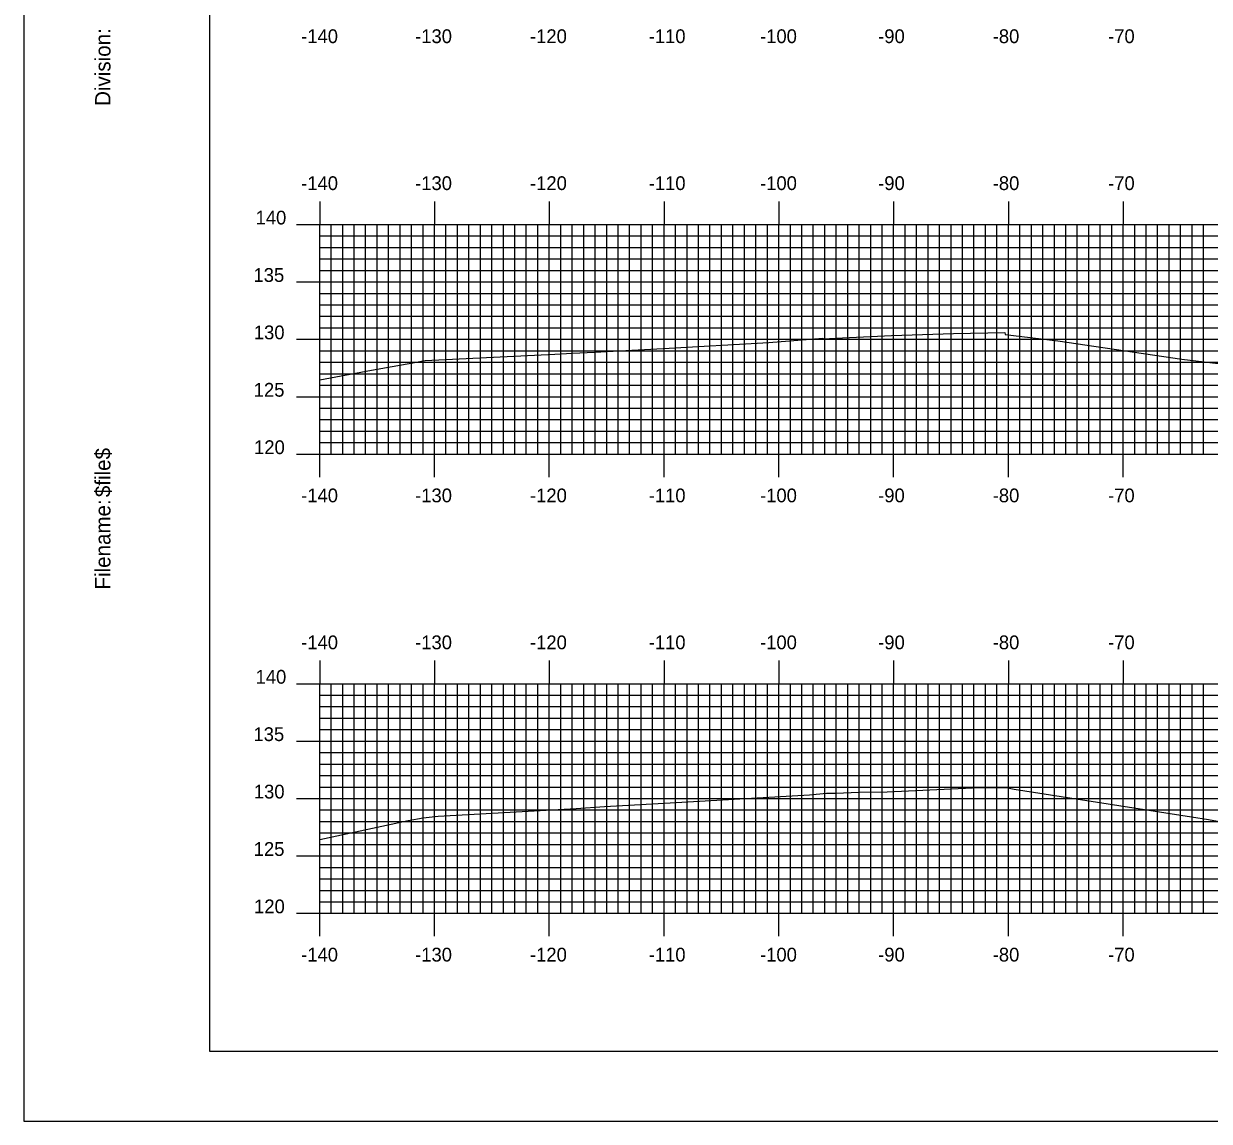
# Model space of a CAD drawing. Extents: x 841388 to 841731, y 363538 to 363758.
# Drawn here: x 841388.1 to 841491.4, y 363537.6 to 363633.2 of the extents above; entities that cross this region are included whole.
import ezdxf

# ---------------------------------------------------------------- set-up
doc = ezdxf.new("R2010")
doc.units = 0
for name, color, linetype in [('BORDER', 7, 'Continuous'), ('H_V ANNOTATION', 7, 'Continuous'), ('M_Roadway_Centerline', 7, 'Continuous'), ('MAJOR', 7, 'Continuous'), ('MINOR', 7, 'Continuous'), ('PLOT BOUNDARY', 7, 'Continuous'), ('S_Roadway_Centerline', 7, 'Continuous')]:
    doc.layers.add(name, color=color, linetype=linetype)

msp = doc.modelspace()

# ---------------------------------------------------------------- linework, layer by layer
at = {"layer": 'BORDER'}
msp.add_lwpolyline([(841404.26, 363543.72), (841724.26, 363543.72), (841724.26, 363753.72), (841404.26, 363753.72)], close=True, dxfattribs=at)
at = {"layer": 'MAJOR'}
for p, q in [((841413.86, 363617.73), (841413.86, 363615.72)), ((841423.86, 363617.73), (841423.86, 363615.72)), ((841433.86, 363617.73), (841433.86, 363615.72)), ((841443.86, 363617.73), (841443.86, 363615.72)), ((841453.86, 363617.73), (841453.86, 363615.72)), ((841463.86, 363617.73), (841463.86, 363615.72)), ((841473.86, 363617.73), (841473.86, 363615.72)), ((841483.86, 363617.73), (841483.86, 363615.72)), ((841411.85, 363615.72), (841413.86, 363615.72)), ((841413.86, 363615.72), (841693.86, 363615.72)), ((841413.86, 363595.72), (841413.86, 363615.72)), ((841413.86, 363595.72), (841413.86, 363615.72)), ((841413.86, 363615.72), (841693.86, 363615.72)), ((841423.86, 363595.72), (841423.86, 363615.72)), ((841433.86, 363595.72), (841433.86, 363615.72)), ((841443.86, 363595.72), (841443.86, 363615.72)), ((841453.86, 363595.72), (841453.86, 363615.72)), ((841463.86, 363595.72), (841463.86, 363615.72)), ((841473.86, 363595.72), (841473.86, 363615.72)), ((841483.86, 363595.72), (841483.86, 363615.72)), ((841411.85, 363610.72), (841413.86, 363610.72)), ((841413.86, 363610.72), (841693.86, 363610.72)), ((841411.85, 363605.72), (841413.86, 363605.72)), ((841413.86, 363605.72), (841693.86, 363605.72)), ((841411.85, 363600.72), (841413.86, 363600.72)), ((841413.86, 363600.72), (841693.86, 363600.72)), ((841411.85, 363595.72), (841413.86, 363595.72)), ((841413.86, 363595.72), (841693.86, 363595.72)), ((841413.86, 363595.72), (841693.86, 363595.72)), ((841413.86, 363593.72), (841413.86, 363595.72)), ((841423.86, 363593.72), (841423.86, 363595.72)), ((841433.86, 363593.72), (841433.86, 363595.72)), ((841443.86, 363593.72), (841443.86, 363595.72)), ((841453.86, 363593.72), (841453.86, 363595.72)), ((841463.86, 363593.72), (841463.86, 363595.72)), ((841473.86, 363593.72), (841473.86, 363595.72)), ((841483.86, 363593.72), (841483.86, 363595.72)), ((841413.86, 363577.73), (841413.86, 363575.72)), ((841423.86, 363577.73), (841423.86, 363575.72)), ((841433.86, 363577.73), (841433.86, 363575.72)), ((841443.86, 363577.73), (841443.86, 363575.72)), ((841453.86, 363577.73), (841453.86, 363575.72)), ((841463.86, 363577.73), (841463.86, 363575.72)), ((841473.86, 363577.73), (841473.86, 363575.72)), ((841483.86, 363577.73), (841483.86, 363575.72)), ((841411.85, 363575.72), (841413.86, 363575.72)), ((841413.86, 363575.72), (841693.86, 363575.72)), ((841413.86, 363555.72), (841413.86, 363575.72)), ((841413.86, 363555.72), (841413.86, 363575.72)), ((841413.86, 363575.72), (841693.86, 363575.72)), ((841423.86, 363555.72), (841423.86, 363575.72)), ((841433.86, 363555.72), (841433.86, 363575.72)), ((841443.86, 363555.72), (841443.86, 363575.72)), ((841453.86, 363555.72), (841453.86, 363575.72)), ((841463.86, 363555.72), (841463.86, 363575.72)), ((841473.86, 363555.72), (841473.86, 363575.72)), ((841483.86, 363555.72), (841483.86, 363575.72)), ((841411.85, 363570.72), (841413.86, 363570.72)), ((841413.86, 363570.72), (841693.86, 363570.72)), ((841411.85, 363565.72), (841413.86, 363565.72)), ((841413.86, 363565.72), (841693.86, 363565.72)), ((841411.85, 363560.72), (841413.86, 363560.72)), ((841413.86, 363560.72), (841693.86, 363560.72)), ((841411.85, 363555.72), (841413.86, 363555.72)), ((841413.86, 363555.72), (841693.86, 363555.72)), ((841413.86, 363555.72), (841693.86, 363555.72)), ((841413.86, 363553.72), (841413.86, 363555.72)), ((841423.86, 363553.72), (841423.86, 363555.72)), ((841433.86, 363553.72), (841433.86, 363555.72)), ((841443.86, 363553.72), (841443.86, 363555.72)), ((841453.86, 363553.72), (841453.86, 363555.72)), ((841463.86, 363553.72), (841463.86, 363555.72)), ((841473.86, 363553.72), (841473.86, 363555.72)), ((841483.86, 363553.72), (841483.86, 363555.72))]:
    msp.add_line(p, q, dxfattribs=at)
at = {"layer": 'MINOR'}
for p, q in [((841414.86, 363595.72), (841414.86, 363615.72)), ((841415.86, 363595.72), (841415.86, 363615.72)), ((841416.86, 363595.72), (841416.86, 363615.72)), ((841417.86, 363595.72), (841417.86, 363615.72)), ((841418.86, 363595.72), (841418.86, 363615.72)), ((841419.86, 363595.72), (841419.86, 363615.72)), ((841420.86, 363595.72), (841420.86, 363615.72)), ((841421.86, 363595.72), (841421.86, 363615.72)), ((841422.86, 363595.72), (841422.86, 363615.72)), ((841424.86, 363595.72), (841424.86, 363615.72)), ((841425.86, 363595.72), (841425.86, 363615.72)), ((841426.86, 363595.72), (841426.86, 363615.72)), ((841427.86, 363595.72), (841427.86, 363615.72)), ((841428.86, 363595.72), (841428.86, 363615.72)), ((841429.86, 363595.72), (841429.86, 363615.72)), ((841430.86, 363595.72), (841430.86, 363615.72)), ((841431.86, 363595.72), (841431.86, 363615.72)), ((841432.86, 363595.72), (841432.86, 363615.72)), ((841434.86, 363595.72), (841434.86, 363615.72)), ((841435.86, 363595.72), (841435.86, 363615.72)), ((841436.86, 363595.72), (841436.86, 363615.72)), ((841437.86, 363595.72), (841437.86, 363615.72)), ((841438.86, 363595.72), (841438.86, 363615.72)), ((841439.86, 363595.72), (841439.86, 363615.72)), ((841440.86, 363595.72), (841440.86, 363615.72)), ((841441.86, 363595.72), (841441.86, 363615.72)), ((841442.86, 363595.72), (841442.86, 363615.72)), ((841444.86, 363595.72), (841444.86, 363615.72)), ((841445.86, 363595.72), (841445.86, 363615.72)), ((841446.86, 363595.72), (841446.86, 363615.72)), ((841447.86, 363595.72), (841447.86, 363615.72)), ((841448.86, 363595.72), (841448.86, 363615.72)), ((841449.86, 363595.72), (841449.86, 363615.72)), ((841450.86, 363595.72), (841450.86, 363615.72)), ((841451.86, 363595.72), (841451.86, 363615.72)), ((841452.86, 363595.72), (841452.86, 363615.72)), ((841454.86, 363595.72), (841454.86, 363615.72)), ((841455.86, 363595.72), (841455.86, 363615.72)), ((841456.86, 363595.72), (841456.86, 363615.72)), ((841457.86, 363595.72), (841457.86, 363615.72)), ((841458.86, 363595.72), (841458.86, 363615.72)), ((841459.86, 363595.72), (841459.86, 363615.72)), ((841460.86, 363595.72), (841460.86, 363615.72)), ((841461.86, 363595.72), (841461.86, 363615.72)), ((841462.86, 363595.72), (841462.86, 363615.72)), ((841464.86, 363595.72), (841464.86, 363615.72)), ((841465.86, 363595.72), (841465.86, 363615.72)), ((841466.86, 363595.72), (841466.86, 363615.72)), ((841467.86, 363595.72), (841467.86, 363615.72)), ((841468.86, 363595.72), (841468.86, 363615.72)), ((841469.86, 363595.72), (841469.86, 363615.72)), ((841470.86, 363595.72), (841470.86, 363615.72)), ((841471.86, 363595.72), (841471.86, 363615.72)), ((841472.86, 363595.72), (841472.86, 363615.72)), ((841474.86, 363595.72), (841474.86, 363615.72)), ((841475.86, 363595.72), (841475.86, 363615.72)), ((841476.86, 363595.72), (841476.86, 363615.72)), ((841477.86, 363595.72), (841477.86, 363615.72)), ((841478.86, 363595.72), (841478.86, 363615.72)), ((841479.86, 363595.72), (841479.86, 363615.72)), ((841480.86, 363595.72), (841480.86, 363615.72)), ((841481.86, 363595.72), (841481.86, 363615.72)), ((841482.86, 363595.72), (841482.86, 363615.72)), ((841484.86, 363595.72), (841484.86, 363615.72)), ((841485.86, 363595.72), (841485.86, 363615.72)), ((841486.86, 363595.72), (841486.86, 363615.72)), ((841487.86, 363595.72), (841487.86, 363615.72)), ((841488.86, 363595.72), (841488.86, 363615.72)), ((841489.86, 363595.72), (841489.86, 363615.72)), ((841490.86, 363595.72), (841490.86, 363615.72)), ((841413.86, 363614.72), (841693.86, 363614.72)), ((841413.86, 363614.72), (841415.86, 363614.72)), ((841413.86, 363613.72), (841693.86, 363613.72)), ((841413.86, 363613.72), (841415.86, 363613.72)), ((841413.86, 363612.72), (841693.86, 363612.72)), ((841413.86, 363612.72), (841415.86, 363612.72)), ((841413.86, 363611.72), (841693.86, 363611.72)), ((841413.86, 363611.72), (841415.86, 363611.72)), ((841413.86, 363609.72), (841693.86, 363609.72)), ((841413.86, 363609.72), (841415.86, 363609.72)), ((841413.86, 363608.72), (841693.86, 363608.72)), ((841413.86, 363608.72), (841415.86, 363608.72)), ((841413.86, 363607.72), (841693.86, 363607.72)), ((841413.86, 363607.72), (841415.86, 363607.72)), ((841413.86, 363606.72), (841693.86, 363606.72)), ((841413.86, 363606.72), (841415.86, 363606.72)), ((841413.86, 363604.72), (841693.86, 363604.72)), ((841413.86, 363604.72), (841415.86, 363604.72)), ((841413.86, 363603.72), (841693.86, 363603.72)), ((841413.86, 363603.72), (841415.86, 363603.72)), ((841413.86, 363602.72), (841693.86, 363602.72)), ((841413.86, 363602.72), (841415.86, 363602.72)), ((841413.86, 363601.72), (841693.86, 363601.72)), ((841413.86, 363601.72), (841415.86, 363601.72)), ((841413.86, 363599.72), (841693.86, 363599.72)), ((841413.86, 363599.72), (841415.86, 363599.72)), ((841413.86, 363598.72), (841693.86, 363598.72)), ((841413.86, 363598.72), (841415.86, 363598.72)), ((841413.86, 363597.72), (841693.86, 363597.72)), ((841413.86, 363597.72), (841415.86, 363597.72)), ((841413.86, 363596.72), (841693.86, 363596.72)), ((841413.86, 363596.72), (841415.86, 363596.72)), ((841414.86, 363555.72), (841414.86, 363575.72)), ((841415.86, 363555.72), (841415.86, 363575.72)), ((841416.86, 363555.72), (841416.86, 363575.72)), ((841417.86, 363555.72), (841417.86, 363575.72)), ((841418.86, 363555.72), (841418.86, 363575.72)), ((841419.86, 363555.72), (841419.86, 363575.72)), ((841420.86, 363555.72), (841420.86, 363575.72)), ((841421.86, 363555.72), (841421.86, 363575.72)), ((841422.86, 363555.72), (841422.86, 363575.72)), ((841424.86, 363555.72), (841424.86, 363575.72)), ((841425.86, 363555.72), (841425.86, 363575.72)), ((841426.86, 363555.72), (841426.86, 363575.72)), ((841427.86, 363555.72), (841427.86, 363575.72)), ((841428.86, 363555.72), (841428.86, 363575.72)), ((841429.86, 363555.72), (841429.86, 363575.72)), ((841430.86, 363555.72), (841430.86, 363575.72)), ((841431.86, 363555.72), (841431.86, 363575.72)), ((841432.86, 363555.72), (841432.86, 363575.72)), ((841434.86, 363555.72), (841434.86, 363575.72)), ((841435.86, 363555.72), (841435.86, 363575.72)), ((841436.86, 363555.72), (841436.86, 363575.72)), ((841437.86, 363555.72), (841437.86, 363575.72)), ((841438.86, 363555.72), (841438.86, 363575.72)), ((841439.86, 363555.72), (841439.86, 363575.72)), ((841440.86, 363555.72), (841440.86, 363575.72)), ((841441.86, 363555.72), (841441.86, 363575.72)), ((841442.86, 363555.72), (841442.86, 363575.72)), ((841444.86, 363555.72), (841444.86, 363575.72)), ((841445.86, 363555.72), (841445.86, 363575.72)), ((841446.86, 363555.72), (841446.86, 363575.72)), ((841447.86, 363555.72), (841447.86, 363575.72)), ((841448.86, 363555.72), (841448.86, 363575.72)), ((841449.86, 363555.72), (841449.86, 363575.72)), ((841450.86, 363555.72), (841450.86, 363575.72)), ((841451.86, 363555.72), (841451.86, 363575.72)), ((841452.86, 363555.72), (841452.86, 363575.72)), ((841454.86, 363555.72), (841454.86, 363575.72)), ((841455.86, 363555.72), (841455.86, 363575.72)), ((841456.86, 363555.72), (841456.86, 363575.72)), ((841457.86, 363555.72), (841457.86, 363575.72)), ((841458.86, 363555.72), (841458.86, 363575.72)), ((841459.86, 363555.72), (841459.86, 363575.72)), ((841460.86, 363555.72), (841460.86, 363575.72)), ((841461.86, 363555.72), (841461.86, 363575.72)), ((841462.86, 363555.72), (841462.86, 363575.72)), ((841464.86, 363555.72), (841464.86, 363575.72)), ((841465.86, 363555.72), (841465.86, 363575.72)), ((841466.86, 363555.72), (841466.86, 363575.72)), ((841467.86, 363555.72), (841467.86, 363575.72)), ((841468.86, 363555.72), (841468.86, 363575.72)), ((841469.86, 363555.72), (841469.86, 363575.72)), ((841470.86, 363555.72), (841470.86, 363575.72)), ((841471.86, 363555.72), (841471.86, 363575.72)), ((841472.86, 363555.72), (841472.86, 363575.72)), ((841474.86, 363555.72), (841474.86, 363575.72)), ((841475.86, 363555.72), (841475.86, 363575.72)), ((841476.86, 363555.72), (841476.86, 363575.72)), ((841477.86, 363555.72), (841477.86, 363575.72)), ((841478.86, 363555.72), (841478.86, 363575.72)), ((841479.86, 363555.72), (841479.86, 363575.72)), ((841480.86, 363555.72), (841480.86, 363575.72)), ((841481.86, 363555.72), (841481.86, 363575.72)), ((841482.86, 363555.72), (841482.86, 363575.72)), ((841484.86, 363555.72), (841484.86, 363575.72)), ((841485.86, 363555.72), (841485.86, 363575.72)), ((841486.86, 363555.72), (841486.86, 363575.72)), ((841487.86, 363555.72), (841487.86, 363575.72)), ((841488.86, 363555.72), (841488.86, 363575.72)), ((841489.86, 363555.72), (841489.86, 363575.72)), ((841490.86, 363555.72), (841490.86, 363575.72)), ((841413.86, 363574.72), (841693.86, 363574.72)), ((841413.86, 363574.72), (841415.86, 363574.72)), ((841413.86, 363573.72), (841693.86, 363573.72)), ((841413.86, 363573.72), (841415.86, 363573.72)), ((841413.86, 363572.72), (841693.86, 363572.72)), ((841413.86, 363572.72), (841415.86, 363572.72)), ((841413.86, 363571.72), (841693.86, 363571.72)), ((841413.86, 363571.72), (841415.86, 363571.72)), ((841413.86, 363569.72), (841693.86, 363569.72)), ((841413.86, 363569.72), (841415.86, 363569.72)), ((841413.86, 363568.72), (841693.86, 363568.72)), ((841413.86, 363568.72), (841415.86, 363568.72)), ((841413.86, 363567.72), (841693.86, 363567.72)), ((841413.86, 363567.72), (841415.86, 363567.72)), ((841413.86, 363566.72), (841693.86, 363566.72)), ((841413.86, 363566.72), (841415.86, 363566.72)), ((841413.86, 363564.72), (841693.86, 363564.72)), ((841413.86, 363564.72), (841415.86, 363564.72)), ((841413.86, 363563.72), (841693.86, 363563.72)), ((841413.86, 363563.72), (841415.86, 363563.72)), ((841413.86, 363562.72), (841693.86, 363562.72)), ((841413.86, 363562.72), (841415.86, 363562.72)), ((841413.86, 363561.72), (841693.86, 363561.72)), ((841413.86, 363561.72), (841415.86, 363561.72)), ((841413.86, 363559.72), (841693.86, 363559.72)), ((841413.86, 363559.72), (841415.86, 363559.72)), ((841413.86, 363558.72), (841693.86, 363558.72)), ((841413.86, 363558.72), (841415.86, 363558.72)), ((841413.86, 363557.72), (841693.86, 363557.72)), ((841413.86, 363557.72), (841415.86, 363557.72)), ((841413.86, 363556.72), (841693.86, 363556.72)), ((841413.86, 363556.72), (841415.86, 363556.72))]:
    msp.add_line(p, q, dxfattribs=at)
at = {"layer": 'PLOT BOUNDARY'}
msp.add_lwpolyline([(841388.07, 363537.6), (841728.07, 363537.6), (841728.07, 363757.6), (841388.07, 363757.6)], close=True, dxfattribs=at)
at = {"layer": 'S_Roadway_Centerline'}
for points in [[(841413.86, 363602.19), (841418.37, 363603.04), (841421.97, 363603.68), (841423.05, 363603.88), (841434.33, 363604.43), (841435.89, 363604.5), (841437.79, 363604.61), (841443.78, 363604.93), (841452.98, 363605.45), (841457.69, 363605.81), (841457.7, 363605.77), (841459.41, 363605.86), (841463.67, 363606.04), (841469.07, 363606.22), (841473.56, 363606.3), (841473.57, 363606.13), (841478.15, 363605.58), (841488.96, 363604), (841501.64, 363602.47)], [(841413.86, 363562.14), (841421.57, 363563.8), (841422.87, 363564.04), (841424.19, 363564.18), (841436.21, 363564.86), (841438.66, 363565.01), (841444.92, 363565.38), (841456.53, 363566.05), (841458.01, 363566.17), (841458.2, 363566.17), (841458.83, 363566.19), (841460.84, 363566.28), (841463.29, 363566.3), (841470.73, 363566.66), (841473.67, 363566.69), (841474.37, 363566.52), (841489.82, 363564.12), (841491.28, 363563.9), (841494.77, 363563.26)]]:
    msp.add_lwpolyline(points, dxfattribs=at)

# ---------------------------------------------------------------- texts
at = {"layer": 'BORDER'}
for s, p in [('Division:', (841395.63, 363626.05)), ('$file$', (841395.63, 363591.97)), ('Filename:', (841395.63, 363583.92))]:
    msp.add_text(s, height=1.339, rotation=90, dxfattribs=at).set_placement(p)
at = {"layer": 'H_V ANNOTATION'}
for s, p in [('-140', (841412.24, 363631.52)), ('-130', (841422.17, 363631.52)), ('-120', (841432.18, 363631.52)), ('-110', (841442.52, 363631.52)), ('-100', (841452.22, 363631.52)), ('-90', (841462.51, 363631.52)), ('-80', (841472.49, 363631.52)), ('-70', (841482.54, 363631.52)), ('-140', (841412.24, 363618.72)), ('-130', (841422.17, 363618.72)), ('-120', (841432.18, 363618.72)), ('-110', (841442.52, 363618.72)), ('-100', (841452.22, 363618.72)), ('-90', (841462.51, 363618.72)), ('-80', (841472.49, 363618.72)), ('-70', (841482.54, 363618.72)), ('140', (841408.27, 363615.72)), ('135', (841408.09, 363610.72)), ('130', (841408.12, 363605.72)), ('125', (841408.11, 363600.72)), ('120', (841408.14, 363595.72)), ('-140', (841412.24, 363591.52)), ('-130', (841422.17, 363591.52)), ('-120', (841432.18, 363591.52)), ('-110', (841442.52, 363591.52)), ('-100', (841452.22, 363591.52)), ('-90', (841462.51, 363591.52)), ('-80', (841472.49, 363591.52)), ('-70', (841482.54, 363591.52)), ('-140', (841412.24, 363578.72)), ('-130', (841422.17, 363578.72)), ('-120', (841432.18, 363578.72)), ('-110', (841442.52, 363578.72)), ('-100', (841452.22, 363578.72)), ('-90', (841462.51, 363578.72)), ('-80', (841472.49, 363578.72)), ('-70', (841482.54, 363578.72)), ('140', (841408.27, 363575.72)), ('135', (841408.09, 363570.72)), ('130', (841408.12, 363565.72)), ('125', (841408.11, 363560.72)), ('120', (841408.14, 363555.72)), ('-140', (841412.24, 363551.52)), ('-130', (841422.17, 363551.52)), ('-120', (841432.18, 363551.52)), ('-110', (841442.52, 363551.52)), ('-100', (841452.22, 363551.52)), ('-90', (841462.51, 363551.52)), ('-80', (841472.49, 363551.52)), ('-70', (841482.54, 363551.52))]:
    msp.add_text(s, height=1.2, dxfattribs=at).set_placement(p)
at = {"layer": 'M_Roadway_Centerline'}
for s, p in [('C', (841457.68, 363605.81)), ('L', (841457.69, 363605.8)), ('C', (841458, 363566.17)), ('L', (841458.01, 363566.16))]:
    msp.add_text(s, height=0.0146, dxfattribs=at).set_placement(p)
at = {"layer": 'MAJOR'}
for p in [(841413.85, 363595.72), (841413.85, 363555.72)]:
    msp.add_text('-', height=0.012, dxfattribs=at).set_placement(p)

doc.saveas('drawing.dxf')
